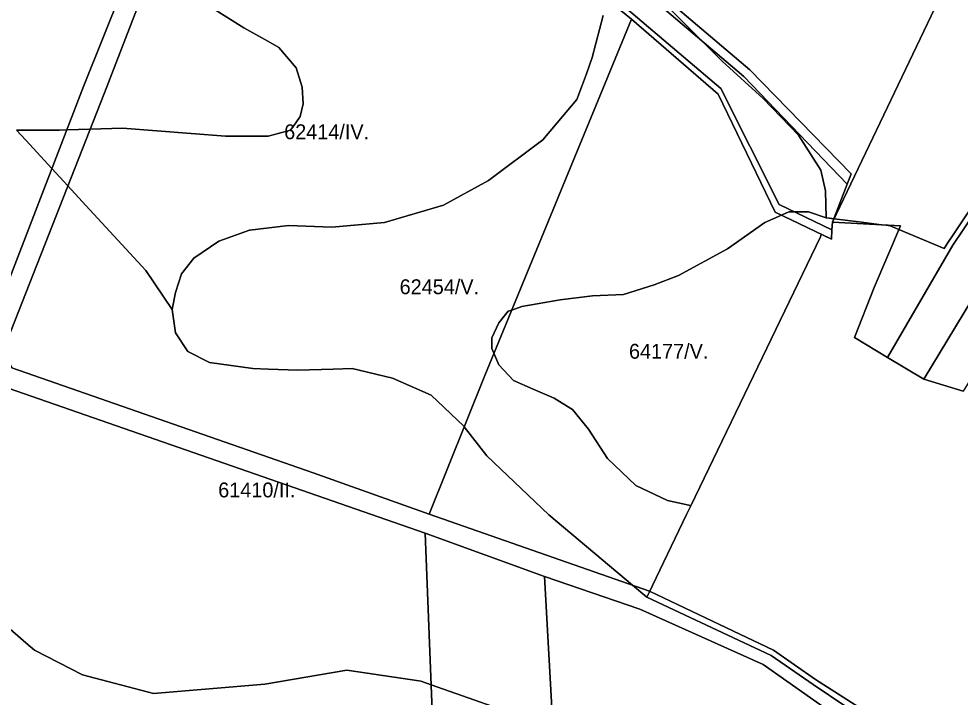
# Model space of a CAD drawing. Extents: x -522079 to -518833, y -1142400 to -1139961.
# Drawn here: x -520002.4 to -519685.2, y -1141371.1 to -1141142.6 of the extents above; entities that cross this region are included whole.
import ezdxf

# ---------------------------------------------------------------- set-up
doc = ezdxf.new("R2010")
doc.units = 0
for name, color, linetype in [('95560013', 7, 'Continuous'), ('95610013', 7, 'Continuous'), ('95620013', 7, 'Continuous'), ('95640013', 7, 'Continuous'), ('95660013', 7, 'Continuous')]:
    doc.layers.add(name, color=color, linetype=linetype)

msp = doc.modelspace()

# ---------------------------------------------------------------- linework, layer by layer
at = {"layer": '95560013'}
for points in [[(-520079.53, -1141019.58), (-520032.33, -1141047.7), (-519951.21, -1141077.01), (-519948.1, -1141084.44), (-519980.55, -1141165.39), (-520014.17, -1141252.24), (-520020.92, -1141254.2), (-520158.56, -1141206.98), (-520129.38, -1141144.09)], [(-519935.26, -1141083.16), (-519941.9, -1141085.78), (-519938.17, -1141076.59), (-519933.25, -1141078.41), (-519920.33, -1141083.18), (-519905.71, -1141088.58), (-519900.64, -1141090.45), (-519884.82, -1141099.57), (-519851.93, -1141096.73), (-519839.81, -1141095.68), (-519827.19, -1141099.4), (-519800.19, -1141122.28), (-519756.03, -1141159.77), (-519721.93, -1141194.85), (-519723.28, -1141198.33), (-519758.08, -1141162.05), (-519828.65, -1141102.04), (-519840, -1141098.37), (-519884.97, -1141102.71), (-519902.89, -1141094.84)], [(-519864.09, -1141309.46), (-519903.26, -1141295.46), (-520004.78, -1141260.17), (-520007.53, -1141254.06), (-519973.57, -1141167.53), (-519941.9, -1141085.78), (-519935.26, -1141083.16), (-519903.85, -1141097.73), (-519880.39, -1141112.19), (-519838.58, -1141107.96), (-519795.94, -1141142.67), (-519845.38, -1141262.74)], [(-519935.26, -1141083.16), (-519902.89, -1141094.84), (-519879.3, -1141109.16), (-519838.27, -1141104.49), (-519765.82, -1141166.07), (-519746.23, -1141205.14), (-519728.39, -1141213.65), (-519728.58, -1141216.84), (-519747.5, -1141207.73), (-519766.69, -1141167.92), (-519795.94, -1141142.67), (-519838.58, -1141107.96), (-519880.39, -1141112.19), (-519903.85, -1141097.73)], [(-519728.23, -1141211.06), (-519728.39, -1141213.65), (-519746.23, -1141205.14), (-519765.82, -1141166.07), (-519838.27, -1141104.49), (-519879.3, -1141109.16), (-519902.89, -1141094.84), (-519884.97, -1141102.71), (-519840, -1141098.37), (-519828.65, -1141102.04), (-519758.08, -1141162.05), (-519723.28, -1141198.33)], [(-519988.83, -1141621.62), (-519993.67, -1141617.6), (-520005.29, -1141383.92), (-520010.89, -1141271.2), (-520005.98, -1141266.96), (-519865.42, -1141315.8), (-519860.18, -1141449.65), (-519851.95, -1141597.5), (-519865.85, -1141595.23), (-519871.86, -1141594.87), (-519890.16, -1141599.67)], [(-519865.42, -1141315.8), (-519825.24, -1141330.38), (-519817.29, -1141473.31), (-519808.88, -1141634.44), (-519812.26, -1141630.88), (-519831.57, -1141610.83), (-519850.96, -1141597.66), (-519851.95, -1141597.5), (-519860.18, -1141449.65)], [(-519825.24, -1141330.38), (-519793.08, -1141341.43), (-519751.63, -1141360.04), (-519727.64, -1141376.95), (-519718.52, -1141529.55), (-519710.49, -1141703.04), (-519778.21, -1141665.51), (-519784.86, -1141659.77), (-519808.88, -1141634.44), (-519817.29, -1141473.31)]]:
    msp.add_lwpolyline(points, close=True, dxfattribs=at)
at = {"layer": '95610013'}
msp.add_lwpolyline([(-519746.51, -1141048.43), (-519749.67, -1141057.47), (-519744.08, -1141063.56), (-519732.93, -1141063.24), (-519729.51, -1141072.8), (-519719.95, -1141075.61), (-519692.8, -1141119.72), (-519691.83, -1141116.63), (-519686.19, -1141123.12), (-519688.75, -1141128.51), (-519728.23, -1141211.06), (-519723.28, -1141198.33), (-519721.93, -1141194.85), (-519756.03, -1141159.77), (-519800.19, -1141122.28), (-519766.87, -1141035.85)], close=True, dxfattribs=at)
at = {"layer": '95620013'}
for points in [[(-519687.67, -1141218.86), (-519709.65, -1141256.63), (-519720.8, -1141249.93), (-519714.2, -1141233.06), (-519705.26, -1141212.3), (-519728.23, -1141211.06), (-519688.75, -1141128.51), (-519686.19, -1141123.12), (-519676.06, -1141134.77), (-519667.13, -1141153.28), (-519663.19, -1141164.28), (-519654.81, -1141169.94)], [(-519697.46, -1141263.95), (-519709.65, -1141256.63), (-519687.67, -1141218.86), (-519654.81, -1141169.94), (-519652.19, -1141178.57), (-519646.01, -1141182.51), (-519676.14, -1141228.74)], [(-519635, -1141188.59), (-519684.2, -1141268.01), (-519697.46, -1141263.95), (-519676.14, -1141228.74), (-519646.01, -1141182.51), (-519637.37, -1141188.02)]]:
    msp.add_lwpolyline(points, close=True, dxfattribs=at)
msp.add_lwpolyline([(-519705.92, -1141383), (-519733.94, -1141365.09), (-519748.09, -1141355.2), (-519766.26, -1141346.58), (-519789.84, -1141335.36), (-519864.09, -1141309.46), (-519845.38, -1141262.74), (-519795.94, -1141142.67), (-519766.69, -1141167.92), (-519747.5, -1141207.73), (-519728.58, -1141216.84), (-519728.39, -1141213.65), (-519728.23, -1141211.06), (-519705.26, -1141212.3), (-519714.2, -1141233.06), (-519720.8, -1141249.93), (-519709.65, -1141256.63), (-519697.46, -1141263.95), (-519684.2, -1141268.01)], dxfattribs=at)
at = {"layer": '95640013'}
msp.add_lwpolyline([(-519980.55, -1141165.39), (-519948.1, -1141084.44), (-519944.08, -1141074.41), (-519938.17, -1141076.59), (-519941.9, -1141085.78), (-519973.57, -1141167.53), (-520007.53, -1141254.06), (-520004.78, -1141260.17), (-520020.92, -1141254.2), (-520014.17, -1141252.24)], close=True, dxfattribs=at)
for points in [[(-520004.78, -1141260.17), (-519903.26, -1141295.46), (-519864.09, -1141309.46), (-519789.84, -1141335.36), (-519766.26, -1141346.58), (-519748.09, -1141355.2), (-519733.94, -1141365.09), (-519705.92, -1141383)], [(-519727.64, -1141376.95), (-519751.63, -1141360.04), (-519793.08, -1141341.43), (-519825.24, -1141330.38), (-519865.42, -1141315.8), (-520005.98, -1141266.96)]]:
    msp.add_lwpolyline(points, dxfattribs=at)
at = {"layer": '95660013'}
for points in [[(-519788.91, -1141133.25), (-519772.01, -1141150.2), (-519765.41, -1141156.82), (-519751.62, -1141169.38), (-519739.72, -1141181.79), (-519732.14, -1141193.58), (-519730.59, -1141200.57), (-519730.38, -1141209.61), (-519736.26, -1141207.57), (-519740.38, -1141207.57), (-519741.13, -1141207.57), (-519742.85, -1141207.57), (-519743.69, -1141207.94), (-519745.44, -1141208.72), (-519751.04, -1141211.22), (-519763.55, -1141220.12), (-519780.16, -1141229.02), (-519788.35, -1141232.21), (-519798.59, -1141235.41), (-519809.05, -1141235.87), (-519819.97, -1141237.24), (-519832.94, -1141239.52), (-519836.31, -1141240.7), (-519837.49, -1141241.11), (-519840.67, -1141245), (-519842.95, -1141250.01), (-519842.95, -1141253.67), (-519842.29, -1141255.24), (-519840.67, -1141259.14), (-519835.67, -1141264.39), (-519829.07, -1141267.36), (-519822.02, -1141270.33), (-519819.3, -1141272.04), (-519815.87, -1141274.2), (-519810.42, -1141280.82), (-519804.05, -1141290.63), (-519794.49, -1141299.76), (-519783.8, -1141304.78), (-519776.68, -1141306.41), (-519775.91, -1141306.58), (-519777.36, -1141309.59), (-519786.36, -1141328.27), (-519788.83, -1141333.41), (-519789.78, -1141335.38), (-519790.77, -1141337.44), (-519795.65, -1141333.33), (-519823.76, -1141309.68), (-519844.65, -1141289.76), (-519852.31, -1141280.04), (-519852.49, -1141279.81), (-519863.46, -1141269.33), (-519876.52, -1141263.57), (-519890.1, -1141260.42), (-519896.48, -1141260.6), (-519908.38, -1141260.95), (-519918.25, -1141260.6), (-519923.52, -1141260.42), (-519938.15, -1141258.33), (-519945.46, -1141254.66), (-519949.64, -1141248.37), (-519950.69, -1141240.51), (-519949.64, -1141234.75), (-519947.55, -1141228.46), (-519943.37, -1141223.22), (-519935.02, -1141217.46), (-519924.64, -1141213.82), (-519924.57, -1141213.79), (-519911.51, -1141212.22), (-519896.89, -1141212.74), (-519879.13, -1141211.17), (-519859.28, -1141205.41), (-519844.13, -1141197.02), (-519825.85, -1141183.4), (-519814.36, -1141169.77), (-519812.81, -1141165.59), (-519811.15, -1141161.1), (-519809.14, -1141155.63), (-519805.48, -1141141.48)], [(-519658.25, -1141171.6), (-519687.52, -1141215.32), (-519689.44, -1141218.2), (-519690.63, -1141219.98), (-519705.81, -1141213.57), (-519708.77, -1141212.32), (-519710.26, -1141212.13), (-519711.69, -1141211.95), (-519718.47, -1141211.1), (-519727.7, -1141209.95), (-519727.78, -1141209.93), (-519728.46, -1141209.85), (-519728.55, -1141209.84), (-519729.22, -1141209.76), (-519730.38, -1141209.61), (-519730.59, -1141200.57), (-519732.14, -1141193.58), (-519739.72, -1141181.79), (-519751.62, -1141169.38), (-519765.41, -1141156.82), (-519772.01, -1141150.2), (-519788.91, -1141133.25)], [(-519938.01, -1141138.42), (-519926.55, -1141145.64), (-519918.49, -1141150.13), (-519914.77, -1141152.2), (-519908.88, -1141159.1), (-519906.92, -1141165.66), (-519906.59, -1141171.24), (-519907.57, -1141175.51), (-519909.08, -1141177.63), (-519910.85, -1141180.1), (-519915.05, -1141181.21), (-519918.37, -1141182.08), (-519932.77, -1141182.08), (-519967.46, -1141179.45), (-519978.38, -1141179.78), (-519986.22, -1141180.03), (-519988.72, -1141180.1), (-520000, -1141180.1), (-520003.12, -1141180.1)], [(-519805.48, -1141141.48), (-519809.14, -1141155.63), (-519811.15, -1141161.1), (-519812.81, -1141165.59), (-519814.36, -1141169.77), (-519825.85, -1141183.4), (-519844.13, -1141197.02), (-519859.28, -1141205.41), (-519879.13, -1141211.17), (-519896.89, -1141212.74), (-519911.51, -1141212.22), (-519924.57, -1141213.79), (-519924.64, -1141213.82), (-519935.02, -1141217.46), (-519943.37, -1141223.22), (-519947.55, -1141228.46), (-519949.64, -1141234.75), (-519950.69, -1141240.51), (-519959.56, -1141227.41), (-519979.78, -1141205.46), (-519985.86, -1141198.85), (-519991.24, -1141193.01), (-520000, -1141183.5), (-520003.12, -1141180.1), (-520000, -1141180.1), (-519988.72, -1141180.1), (-519986.22, -1141180.03), (-519978.38, -1141179.78), (-519967.46, -1141179.45), (-519932.77, -1141182.08), (-519918.37, -1141182.08), (-519915.05, -1141181.21), (-519910.85, -1141180.1), (-519909.08, -1141177.63), (-519907.57, -1141175.51), (-519906.59, -1141171.24), (-519906.92, -1141165.66), (-519908.88, -1141159.1), (-519914.77, -1141152.2), (-519918.49, -1141150.13), (-519926.55, -1141145.64), (-519938.01, -1141138.42)], [(-519723.37, -1141374.45), (-519734.68, -1141366.82), (-519748.86, -1141356.99), (-519790.77, -1141337.44), (-519789.78, -1141335.38), (-519788.83, -1141333.41), (-519786.36, -1141328.27), (-519777.36, -1141309.59), (-519775.91, -1141306.58), (-519732.26, -1141215.97), (-519732.04, -1141215.17), (-519728.58, -1141216.84), (-519728.39, -1141213.65), (-519728.23, -1141211.06), (-519727.7, -1141209.95), (-519718.47, -1141211.1), (-519711.69, -1141211.95), (-519710.26, -1141212.13), (-519708.77, -1141212.32), (-519705.81, -1141213.57), (-519690.63, -1141219.98), (-519689.44, -1141218.2), (-519687.52, -1141215.32), (-519658.25, -1141171.6)], [(-520003.12, -1141180.1), (-520000, -1141183.5), (-519991.24, -1141193.01), (-519985.86, -1141198.85), (-519979.78, -1141205.46), (-519959.56, -1141227.41), (-519950.69, -1141240.51), (-519949.64, -1141248.37), (-519945.46, -1141254.66), (-519938.15, -1141258.33), (-519923.52, -1141260.42), (-519918.25, -1141260.6), (-519908.38, -1141260.95), (-519896.48, -1141260.6), (-519890.1, -1141260.42), (-519876.52, -1141263.57), (-519863.46, -1141269.33), (-519852.49, -1141279.81), (-519852.31, -1141280.04), (-519844.65, -1141289.76), (-519823.76, -1141309.68), (-519795.65, -1141333.33), (-519790.77, -1141337.44), (-519748.86, -1141356.99), (-519734.68, -1141366.82), (-519723.37, -1141374.45)], [(-520007.15, -1141346.54), (-520000, -1141352.72), (-519997.12, -1141355.21), (-519980.97, -1141363.57), (-519957.01, -1141369.84), (-519919.49, -1141366.7), (-519891.88, -1141362), (-519866.87, -1141365.66), (-519866.55, -1141365.77), (-519863.42, -1141366.88), (-519828.32, -1141379.25)], [(-519828.32, -1141379.25), (-519863.42, -1141366.88), (-519866.55, -1141365.77), (-519866.87, -1141365.66), (-519891.88, -1141362), (-519919.49, -1141366.7), (-519957.01, -1141369.84), (-519980.97, -1141363.57), (-519997.12, -1141355.21), (-520000, -1141352.72), (-520007.15, -1141346.54)]]:
    msp.add_lwpolyline(points, dxfattribs=at)
msp.add_lwpolyline([(-519730.38, -1141209.61), (-519729.22, -1141209.76), (-519728.55, -1141209.84), (-519728.46, -1141209.85), (-519727.78, -1141209.93), (-519727.7, -1141209.95), (-519728.23, -1141211.06), (-519728.39, -1141213.65), (-519728.58, -1141216.84), (-519732.04, -1141215.17), (-519732.26, -1141215.97), (-519775.91, -1141306.58), (-519776.68, -1141306.41), (-519783.8, -1141304.78), (-519794.49, -1141299.76), (-519804.05, -1141290.63), (-519810.42, -1141280.82), (-519815.87, -1141274.2), (-519819.3, -1141272.04), (-519822.02, -1141270.33), (-519829.07, -1141267.36), (-519835.67, -1141264.39), (-519840.67, -1141259.14), (-519842.29, -1141255.24), (-519842.95, -1141253.67), (-519842.95, -1141250.01), (-519840.67, -1141245), (-519837.49, -1141241.11), (-519836.31, -1141240.7), (-519832.94, -1141239.52), (-519819.97, -1141237.24), (-519809.05, -1141235.87), (-519798.59, -1141235.41), (-519788.35, -1141232.21), (-519780.16, -1141229.02), (-519763.55, -1141220.12), (-519751.04, -1141211.22), (-519745.44, -1141208.72), (-519743.69, -1141207.94), (-519742.85, -1141207.57), (-519741.13, -1141207.57), (-519740.38, -1141207.57), (-519736.26, -1141207.57)], close=True, dxfattribs=at)

# ---------------------------------------------------------------- texts
for s, rotation, p in [('62414/IV.', 360, (-519912.98, -1141183.14)), ('62454/V.', 360, (-519874.07, -1141235.34)), ('64177/V.', 0, (-519796.79, -1141257.07)), ('61410/II.', 0, (-519935.2, -1141303.77))]:
    msp.add_text(s, height=5, rotation=rotation, dxfattribs=at).set_placement(p)

doc.saveas('drawing.dxf')
